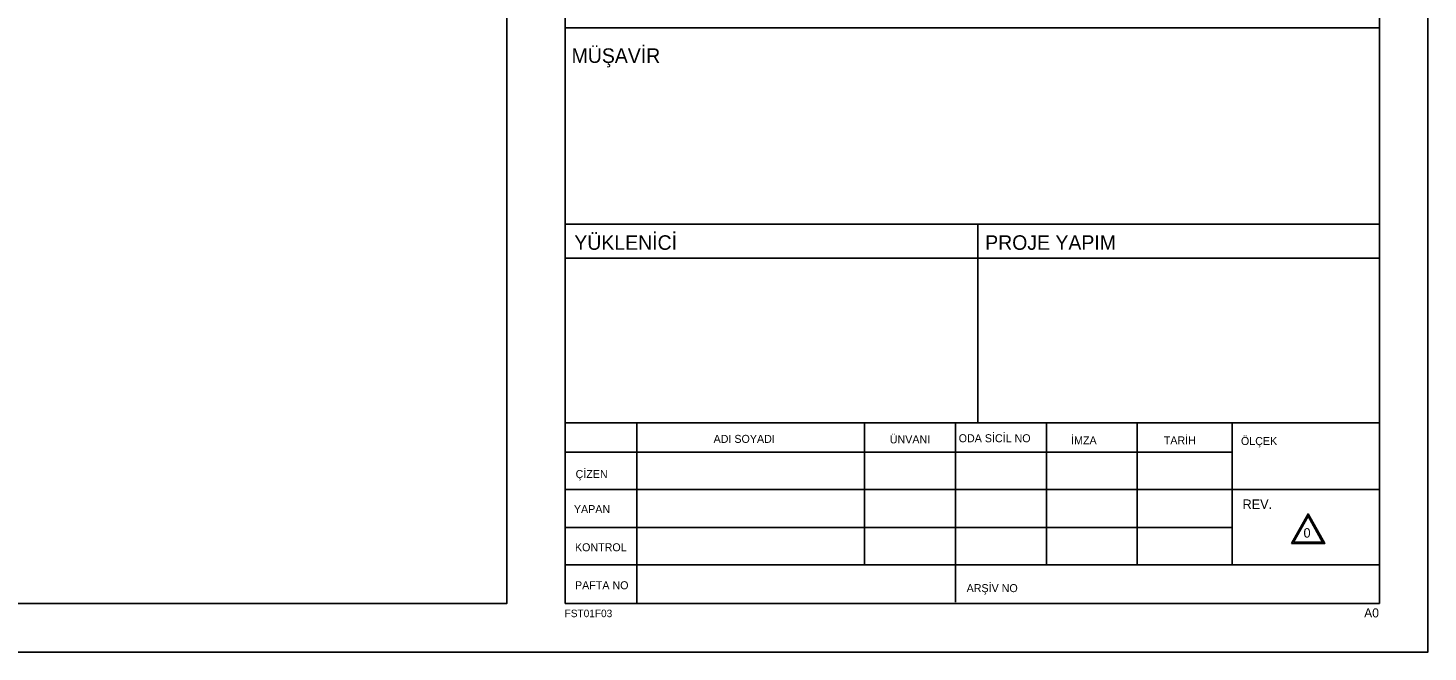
# Model space of a CAD drawing. Extents: x -10 to 1145, y -10 to 821.
# Drawn here: x 856.2 to 1145, y -10 to 118.8 of the extents above; entities that cross this region are included whole.
import ezdxf

# ---------------------------------------------------------------- set-up
doc = ezdxf.new("R2010")
doc.units = 0
for name, color, linetype in [('Level 20', 7, 'Continuous'), ('Level 50', 7, 'Continuous'), ('Level 51', 7, 'Continuous'), ('Level 6', 7, 'Continuous'), ('Level 7', 7, 'Continuous')]:
    doc.layers.add(name, color=color, linetype=linetype)

msp = doc.modelspace()

# ---------------------------------------------------------------- linework, layer by layer
at = {"layer": 'Level 20'}
msp.add_line((1052.15, 37.22), (1052.15, 78.24), dxfattribs=at)
at = {"layer": 'Level 50'}
msp.add_lwpolyline([(0, 0), (955, 0), (955, 811), (0, 811)], close=True, dxfattribs=at)
at = {"layer": 'Level 51'}
msp.add_lwpolyline([(-10, -10), (1145, -10), (1145, 821), (-10, 821)], close=True, dxfattribs=at)
at = {"layer": 'Level 6'}
for p, q in [((967.03, 0), (967.03, 262.93)), ((1135, 0), (1135, 262.93)), ((1135, 0), (1135, 262.93)), ((1135, 0), (1135, 262.93)), ((1135, 0), (1135, 262.93)), ((967.03, 118.78), (1135, 118.78)), ((967.03, 78.28), (1135, 78.28)), ((967.03, 71.28), (1135, 71.28)), ((967.03, 37.27), (1135, 37.27)), ((967.03, 37.27), (1135, 37.27)), ((967.03, 37.27), (1135, 37.27)), ((967.03, 37.27), (1135, 37.27)), ((981.8, 0), (981.8, 37.13)), ((1028.79, 7.98), (1028.79, 37.27)), ((1047.54, 0.32), (1047.54, 37.27)), ((1066.29, 8.15), (1066.29, 37.27)), ((1085.04, 8.15), (1085.04, 37.27)), ((1104.62, 37.27), (1104.62, 7.98)), ((967.03, 31.27), (1104.38, 31.27)), ((967.03, 31.27), (1076.74, 31.27)), ((967.03, 31.27), (1076.74, 31.27)), ((967.03, 31.27), (1076.74, 31.27)), ((966.89, 23.52), (1134.87, 23.52)), ((967.03, 15.73), (1104.62, 15.73)), ((967.03, 7.98), (1134.87, 7.98)), ((967.03, 0), (1135, 0)), ((967.03, 0), (1135, 0)), ((967.03, 0), (1135, 0)), ((967.03, 0), (1135, 0)), ((967.03, 0), (1135, 0)), ((967.03, 0), (1135, 0)), ((967.03, 0), (1135, 0)), ((967.03, 0), (1135, 0))]:
    msp.add_line(p, q, dxfattribs=at)
at = {"layer": 'Level 7'}
for points in [[(1116.85, 12.39), (1120.27, 18.51), (1123.69, 12.39)], [(1116.85, 12.39), (1120.27, 18.51), (1123.69, 12.39)], [(1116.85, 12.39), (1120.27, 18.51), (1123.69, 12.39)], [(1116.85, 12.39), (1120.27, 18.51), (1123.69, 12.39)], [(1117.28, 12.64), (1120.27, 18.01), (1123.27, 12.64)], [(1117.28, 12.64), (1120.27, 18.01), (1123.27, 12.64)], [(1117.28, 12.64), (1120.27, 18.01), (1123.27, 12.64)], [(1117.28, 12.64), (1120.27, 18.01), (1123.27, 12.64)]]:
    msp.add_lwpolyline(points, close=True, dxfattribs=at)

# ---------------------------------------------------------------- texts
for s, height, p in [('MÜŞAVİR', 3, (968.37, 111.57)), ('YÜKLENİCİ', 3, (968.93, 73)), ('PROJE YAPIM', 3, (1053.67, 73)), ('ADI SOYADI', 1.65, (997.65, 33.16)), ('ÜNVANI', 1.65, (1033.99, 33.06)), ('ODA SİCİL NO', 1.65, (1048.2, 33.29)), ('İMZA', 1.65, (1071.39, 32.85)), ('TARİH', 1.65, (1090.5, 32.85)), ('ÖLÇEK', 1.65, (1106.42, 32.72)), ('ÇİZEN', 1.65, (969.19, 25.91)), ('YAPAN', 1.65, (968.84, 18.67)), ('REV.', 1.951, (1106.76, 19.53)), ('0', 1.95, (1119.33, 13.61)), ('KONTROL', 1.65, (969.06, 10.79)), ('PAFTA NO', 1.65, (969.07, 2.95)), ('ARŞİV NO', 1.65, (1049.84, 2.36)), ('FST01F03', 1.555, (966.93, -2.81)), ('A0', 1.866, (1131.83, -2.86))]:
    msp.add_text(s, height=height, dxfattribs=at).set_placement(p)

doc.saveas('drawing.dxf')
